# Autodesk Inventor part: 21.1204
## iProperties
Created: 2006-02
Part Number: 21.1204
Material: Steel, Mild
Description: M8 x 25 SHCS
Document SubType Name: Modeling
Standard: DIN 7984
Designer: Andy Moles
Standards Organization: DIN
Language: en-US
Size Designation: M8 x 25
Categories: <MemberInstance><Categories><Category DisplayName="Fasteners" InternalName="e4da775c-781d-43d5-af7c-5136215cf5a6" Mnemonic="FSTN"><Category DisplayName="Bolts"
Density: 7.86 g/cm^3
Mass: 14.2385 g
Surface Area: 11.4333 cm^2
Volume: 1.81151 cm^3
Vendor: S
Author: Andy Moles
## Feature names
1. Body [Revolution]
2. Slot [Extrusion]
3. Fillet1
4. Chamfer1
